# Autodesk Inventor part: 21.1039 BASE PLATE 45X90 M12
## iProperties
Created: 2007-03
Part Number: 21.1039 BASE PLATE 45X90 M12
Document SubType Name: Modeling
Designer: Andy Moles
Material: Aluminum-6061
Mass: 150.321 g
Surface Area: 129.274 cm^2
Volume: 55.4689 cm^3
Density: 2.71 g/cm^3
Author: Andy Moles
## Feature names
1. Extrusion1
2. Hole1
3. Hole2
4. Fillet1
